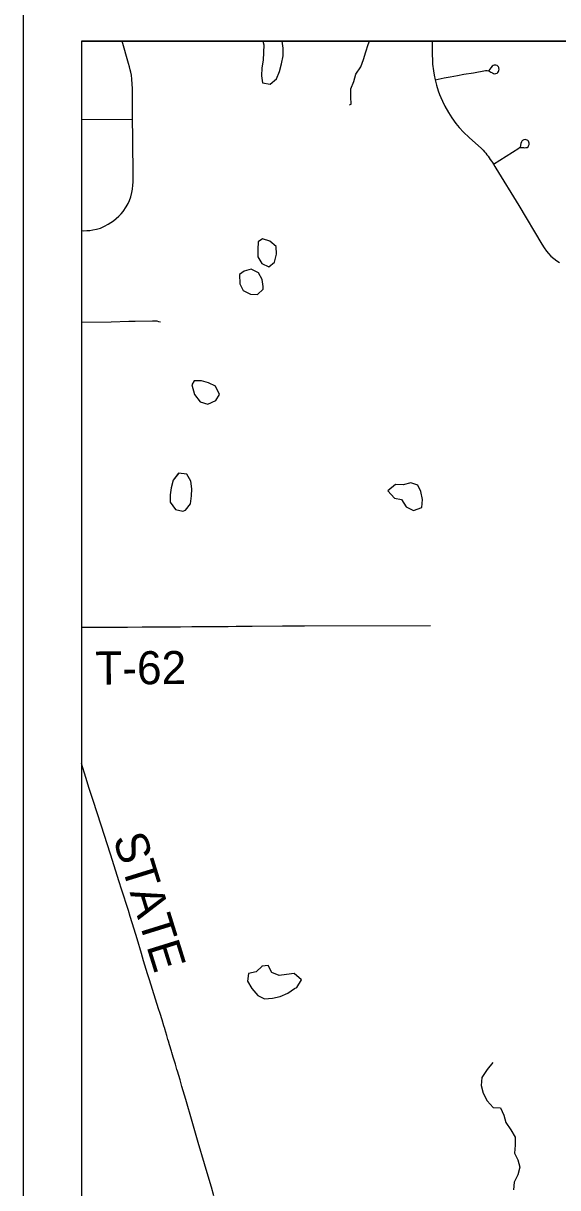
# Model space of a CAD drawing. Extents: x 0 to 34, y 0 to 22.
# Drawn here: x 2 to 2.919, y 18.93 to 20.931 of the extents above; entities that cross this region are included whole.
import ezdxf

# ---------------------------------------------------------------- set-up
doc = ezdxf.new("R2010")
doc.units = 0
for name, color, linetype in [('Default', 7, 'Continuous'), ('GM_X_County_Road', 7, 'Continuous'), ('GM_X_County_Road_Text', 7, 'Continuous'), ('GM_X_Minor_Lake', 7, 'Continuous'), ('GM_X_Minor_River', 7, 'Continuous'), ('GM_X_Township_Road', 7, 'Continuous'), ('GM_X_Township_Road_Text', 7, 'Continuous'), ('SH_Cut_Line', 7, 'Continuous'), ('SH_Data', 7, 'Continuous')]:
    doc.layers.add(name, color=color, linetype=linetype)

msp = doc.modelspace()

# ---------------------------------------------------------------- linework, layer by layer
at = {"layer": 'Default'}
msp.add_lwpolyline([(3.2826, 20.9), (2.1, 20.9), (2.1, 15.8248), (3.2829, 15.8433), (3.2832, 16.3898), (3.2835, 17.0107), (3.2837, 17.3796), (3.2907, 18.4315), (3.2904, 19.1173), (3.2901, 19.68), (3.2888, 19.8918), (3.2845, 20.5998), (3.2843, 20.6124)], close=True, dxfattribs=at)
at = {"layer": 'GM_X_County_Road'}
msp.add_lwpolyline([(2.3278, 18.9158), (2.3234, 18.9309), (2.3128, 18.967), (2.3116, 18.971), (2.3009, 19.0076), (2.2903, 19.0438), (2.2794, 19.0812), (2.2727, 19.1039), (2.2694, 19.1151), (2.2671, 19.123), (2.2649, 19.1304), (2.2641, 19.1333), (2.2614, 19.1423), (2.2578, 19.1545), (2.2555, 19.1621), (2.2548, 19.1646), (2.2543, 19.1664), (2.2522, 19.1735), (2.2516, 19.1753), (2.2497, 19.1816), (2.2487, 19.1848), (2.2468, 19.1913), (2.2433, 19.2028), (2.2431, 19.2034), (2.2418, 19.2079), (2.2385, 19.2186), (2.2353, 19.2292), (2.2326, 19.2375), (2.2222, 19.2703), (2.2169, 19.287), (2.2137, 19.2972), (2.2069, 19.32), (2.2032, 19.3321), (2.1955, 19.3577), (2.1907, 19.3741), (2.1872, 19.3851), (2.184, 19.3958), (2.1807, 19.4062), (2.1688, 19.443), (2.1649, 19.4555), (2.1497, 19.5029), (2.1337, 19.5526), (2.12, 19.5953), (2.1135, 19.6159), (2.1077, 19.6347), (2.1, 19.6587)], dxfattribs=at)
at = {"layer": 'GM_X_Minor_Lake'}
for points in [[(2.4118, 20.9), (2.4134, 20.8939), (2.4132, 20.8806), (2.4123, 20.8673), (2.4102, 20.8543), (2.4096, 20.8407), (2.4113, 20.8285)], [(2.4118, 20.9), (2.4134, 20.8939), (2.4132, 20.8806), (2.4123, 20.8673), (2.4102, 20.8543), (2.4096, 20.8407), (2.4113, 20.8285)], [(2.4113, 20.8285), (2.4243, 20.826), (2.4351, 20.8353), (2.4406, 20.848), (2.4439, 20.8609), (2.4467, 20.8747), (2.4469, 20.888), (2.4452, 20.9)], [(2.4113, 20.8285), (2.4243, 20.826), (2.4351, 20.8353), (2.4406, 20.848), (2.4439, 20.8609), (2.4467, 20.8747), (2.4469, 20.888), (2.4452, 20.9)], [(2.4037, 20.5551), (2.4032, 20.5421), (2.403, 20.5292), (2.41, 20.5179), (2.4222, 20.5124)], [(2.4037, 20.5551), (2.4032, 20.5421), (2.403, 20.5292), (2.41, 20.5179), (2.4222, 20.5124)], [(2.4222, 20.5124), (2.4316, 20.5205), (2.4352, 20.5342), (2.4346, 20.5472), (2.4238, 20.5561), (2.4112, 20.5601), (2.4037, 20.5551)], [(2.4222, 20.5124), (2.4316, 20.5205), (2.4352, 20.5342), (2.4346, 20.5472), (2.4238, 20.5561), (2.4112, 20.5601), (2.4037, 20.5551)], [(2.4122, 20.4738), (2.4125, 20.4784), (2.4104, 20.4905), (2.4042, 20.5022), (2.3915, 20.5085), (2.3798, 20.5045), (2.3719, 20.4991)], [(2.4122, 20.4738), (2.4125, 20.4784), (2.4104, 20.4905), (2.4042, 20.5022), (2.3915, 20.5085), (2.3798, 20.5045), (2.3719, 20.499)], [(2.3719, 20.4991), (2.3722, 20.4831), (2.3777, 20.4714), (2.3903, 20.4655), (2.4025, 20.4646), (2.4122, 20.4738)], [(2.3719, 20.499), (2.3722, 20.4831), (2.3777, 20.4714), (2.3903, 20.4655), (2.4025, 20.4646), (2.4122, 20.4738)], [(2.3308, 20.2825), (2.3375, 20.2929), (2.3305, 20.3069), (2.3186, 20.3128), (2.3064, 20.3164), (2.2935, 20.3162), (2.2898, 20.3095)], [(2.3308, 20.2825), (2.3375, 20.2929), (2.3305, 20.3069), (2.3186, 20.3128), (2.3064, 20.3164), (2.2935, 20.3162), (2.2898, 20.3095)], [(2.2898, 20.3096), (2.2946, 20.293), (2.3043, 20.2803), (2.3173, 20.2763), (2.3308, 20.2825)], [(2.2898, 20.3095), (2.2946, 20.293), (2.3043, 20.2803), (2.3173, 20.2763), (2.3308, 20.2825)], [(2.2669, 20.1575), (2.2574, 20.1457), (2.2542, 20.1324), (2.2524, 20.1206), (2.2526, 20.1077), (2.2616, 20.0952), (2.2745, 20.0924)], [(2.2669, 20.1574), (2.2574, 20.1457), (2.2542, 20.1324), (2.2524, 20.1206), (2.2526, 20.1077), (2.2616, 20.0952), (2.2745, 20.0924)], [(2.2745, 20.0924), (2.279, 20.094), (2.2876, 20.1051), (2.2893, 20.1185), (2.2899, 20.131), (2.2882, 20.1439), (2.2811, 20.156), (2.2669, 20.1575)], [(2.2745, 20.0924), (2.279, 20.094), (2.2876, 20.1051), (2.2893, 20.1185), (2.2899, 20.131), (2.2882, 20.1439), (2.2811, 20.156), (2.2669, 20.1575)], [(2.6708, 20.0933), (2.6848, 20.0989), (2.6865, 20.1126), (2.6836, 20.1259), (2.6781, 20.1372), (2.6659, 20.1408), (2.653, 20.1376), (2.6397, 20.1385), (2.6266, 20.1272)], [(2.6708, 20.0933), (2.6848, 20.0989), (2.6865, 20.1126), (2.6836, 20.1259), (2.6781, 20.1372), (2.6659, 20.1408), (2.653, 20.1376), (2.6397, 20.1385), (2.6266, 20.1272)], [(2.6265, 20.1273), (2.6382, 20.1149), (2.6504, 20.1124), (2.6582, 20.0996), (2.6708, 20.0933)], [(2.6266, 20.1272), (2.6382, 20.1149), (2.6504, 20.1124), (2.6582, 20.0996), (2.6708, 20.0933)], [(2.4104, 19.3104), (2.4001, 19.3009), (2.3872, 19.298), (2.3855, 19.2847), (2.3929, 19.2723), (2.403, 19.2602), (2.4148, 19.2547), (2.4285, 19.2557), (2.4414, 19.2585), (2.4546, 19.2641), (2.4662, 19.2722)], [(2.4104, 19.3104), (2.4001, 19.3009), (2.3872, 19.298), (2.3855, 19.2847), (2.3929, 19.2723), (2.403, 19.2602), (2.4148, 19.2547), (2.4285, 19.2557), (2.4414, 19.2585), (2.4546, 19.2641), (2.4662, 19.2722)], [(2.4662, 19.2722), (2.47, 19.2742), (2.4781, 19.2872), (2.4658, 19.2977), (2.4522, 19.2963), (2.44, 19.2943), (2.4274, 19.2998), (2.4208, 19.3115), (2.4103, 19.3104)], [(2.4662, 19.2722), (2.47, 19.2742), (2.4781, 19.2872), (2.4658, 19.2977), (2.4522, 19.2963), (2.44, 19.2943), (2.4274, 19.2998), (2.4208, 19.3115), (2.4104, 19.3104)]]:
    msp.add_lwpolyline(points, dxfattribs=at)
at = {"layer": 'GM_X_Minor_River'}
for points in [[(2.561, 20.7903), (2.5634, 20.792), (2.5628, 20.8042), (2.563, 20.8178), (2.5681, 20.8305), (2.5717, 20.8434), (2.5802, 20.8557), (2.585, 20.8687), (2.5886, 20.8817), (2.5929, 20.8943), (2.5952, 20.9)], [(2.8069, 19.1449), (2.7972, 19.1328), (2.7881, 19.1195), (2.787, 19.1058), (2.7904, 19.0921), (2.7973, 19.0792), (2.8076, 19.0678), (2.8205, 19.067), (2.8258, 19.0545), (2.8293, 19.0419), (2.838, 19.0294), (2.8457, 19.0169), (2.8457, 19.0032), (2.8442, 18.9895), (2.8503, 18.9777), (2.8534, 18.9652), (2.85, 18.9522), (2.8439, 18.9397), (2.8424, 18.926)]]:
    msp.add_lwpolyline(points, dxfattribs=at)
at = {"layer": 'GM_X_Township_Road'}
msp.add_line((2.1, 20.7653), (2.1879, 20.7662), dxfattribs=at)
for points in [[(2.1, 20.5745), (2.1027, 20.5743), (2.1091, 20.5746), (2.1143, 20.5749), (2.1198, 20.5758), (2.126, 20.577), (2.1326, 20.5788), (2.1397, 20.5819), (2.1461, 20.5853), (2.1551, 20.5914), (2.1597, 20.5951), (2.164, 20.599), (2.168, 20.6033), (2.1715, 20.6074), (2.1768, 20.6152), (2.1801, 20.6212), (2.1825, 20.6264), (2.1847, 20.6325), (2.1868, 20.6397), (2.1879, 20.6456), (2.1885, 20.6523), (2.1888, 20.6575), (2.189, 20.6639), (2.1884, 20.7344), (2.1879, 20.7662), (2.1877, 20.8188), (2.1873, 20.8262), (2.1866, 20.8348), (2.1858, 20.8417), (2.1848, 20.8466), (2.1838, 20.8506), (2.1824, 20.8561), (2.1809, 20.8615), (2.1698, 20.9)], [(2.7027, 20.9), (2.7031, 20.875), (2.7033, 20.8695), (2.7037, 20.8606), (2.705, 20.849), (2.7064, 20.8413), (2.7082, 20.8336), (2.7102, 20.8245), (2.7134, 20.8146), (2.7156, 20.8086), (2.7178, 20.803), (2.7205, 20.7971), (2.7246, 20.7885), (2.7307, 20.7776), (2.7367, 20.7683), (2.7437, 20.7584), (2.7492, 20.7519), (2.7568, 20.7438), (2.7663, 20.7347), (2.7878, 20.7153), (2.7907, 20.7125), (2.7928, 20.7099), (2.7949, 20.7074), (2.797, 20.7048), (2.799, 20.7021), (2.8009, 20.6995), (2.8028, 20.6968), (2.8047, 20.694), (2.8065, 20.6913), (2.8083, 20.6885), (2.8106, 20.6847), (2.8123, 20.6819), (2.8518, 20.6177), (2.8912, 20.5514), (2.8952, 20.545), (2.8996, 20.5389), (2.9029, 20.535), (2.9069, 20.5306), (2.9117, 20.5266), (2.9171, 20.5224), (2.9217, 20.5194)], [(2.7082, 20.8336), (2.7234, 20.8368), (2.7338, 20.8389), (2.7463, 20.8411), (2.7573, 20.8431), (2.7741, 20.8457), (2.7944, 20.8493), (2.7972, 20.8495), (2.7997, 20.8489), (2.8018, 20.8478), (2.8039, 20.8465), (2.8063, 20.8454), (2.8083, 20.8444), (2.8106, 20.8441), (2.8125, 20.8443), (2.8143, 20.8451), (2.8158, 20.8463), (2.8168, 20.8479), (2.8175, 20.8497), (2.8178, 20.8517), (2.8176, 20.8533), (2.8174, 20.8546), (2.8169, 20.8558), (2.8159, 20.8572), (2.8143, 20.8581), (2.812, 20.8588), (2.8095, 20.8587), (2.8076, 20.8579), (2.8061, 20.857), (2.8036, 20.854), (2.8002, 20.8497)], [(2.8083, 20.6885), (2.8518, 20.7163), (2.8531, 20.717), (2.8549, 20.7175), (2.8571, 20.7173), (2.8596, 20.717), (2.8613, 20.7169), (2.8638, 20.717), (2.8659, 20.7175), (2.8677, 20.7187), (2.8686, 20.7199), (2.8695, 20.7222), (2.8697, 20.7245), (2.8692, 20.7266), (2.8683, 20.7283), (2.8672, 20.7294), (2.8659, 20.7301), (2.8646, 20.7305), (2.8628, 20.7309), (2.8604, 20.7307), (2.8581, 20.7295), (2.8568, 20.728), (2.8562, 20.727), (2.8552, 20.7239), (2.8539, 20.7176)], [(2.1, 20.417), (2.1509, 20.418), (2.1812, 20.4186), (2.1923, 20.4188), (2.2222, 20.4195), (2.2293, 20.4192), (2.2326, 20.4184), (2.2357, 20.4177)], [(2.1, 19.8929), (2.1793, 19.8933), (2.2043, 19.8935), (2.2128, 19.8935), (2.2279, 19.8936), (2.2457, 19.8938), (2.2704, 19.8939), (2.2897, 19.8941), (2.3087, 19.8942), (2.3251, 19.8943), (2.352, 19.8945), (2.366, 19.8946), (2.3932, 19.8948), (2.4456, 19.8952), (2.4706, 19.8954), (2.4836, 19.8955), (2.7001, 19.8961)]]:
    msp.add_lwpolyline(points, dxfattribs=at)
at = {"layer": 'SH_Cut_Line'}
msp.add_lwpolyline([(3.2826, 20.9), (2.1, 20.9), (2.1, 14.1), (3.2807, 14.1), (3.2808, 14.1155), (3.2822, 14.2781), (3.2841, 14.501), (3.2832, 14.8896), (3.2811, 15.7294), (3.2815, 15.7537), (3.2829, 15.8433), (3.2832, 16.3898), (3.2835, 17.0107), (3.2837, 17.3796), (3.2907, 18.4315), (3.2904, 19.1173), (3.2901, 19.68), (3.2888, 19.8918), (3.2845, 20.5998), (3.2843, 20.6124)], close=True, dxfattribs=at)
at = {"layer": 'SH_Data'}
for p, q in [((2, 21), (2, 14)), ((2.1, 20.9), (2.1, 14.1)), ((2.1, 20.9), (8.9, 20.9))]:
    msp.add_line(p, q, dxfattribs=at)

# ---------------------------------------------------------------- texts
at = {"layer": 'GM_X_County_Road_Text'}
msp.add_text('STATE', height=0.05682, rotation=287.2486, dxfattribs=at).set_placement((2.1538, 19.5305))
at = {"layer": 'GM_X_Township_Road_Text'}
msp.add_text('T-62', height=0.05682, rotation=0.3535, dxfattribs=at).set_placement((2.1239, 19.7944))

doc.saveas('drawing.dxf')
